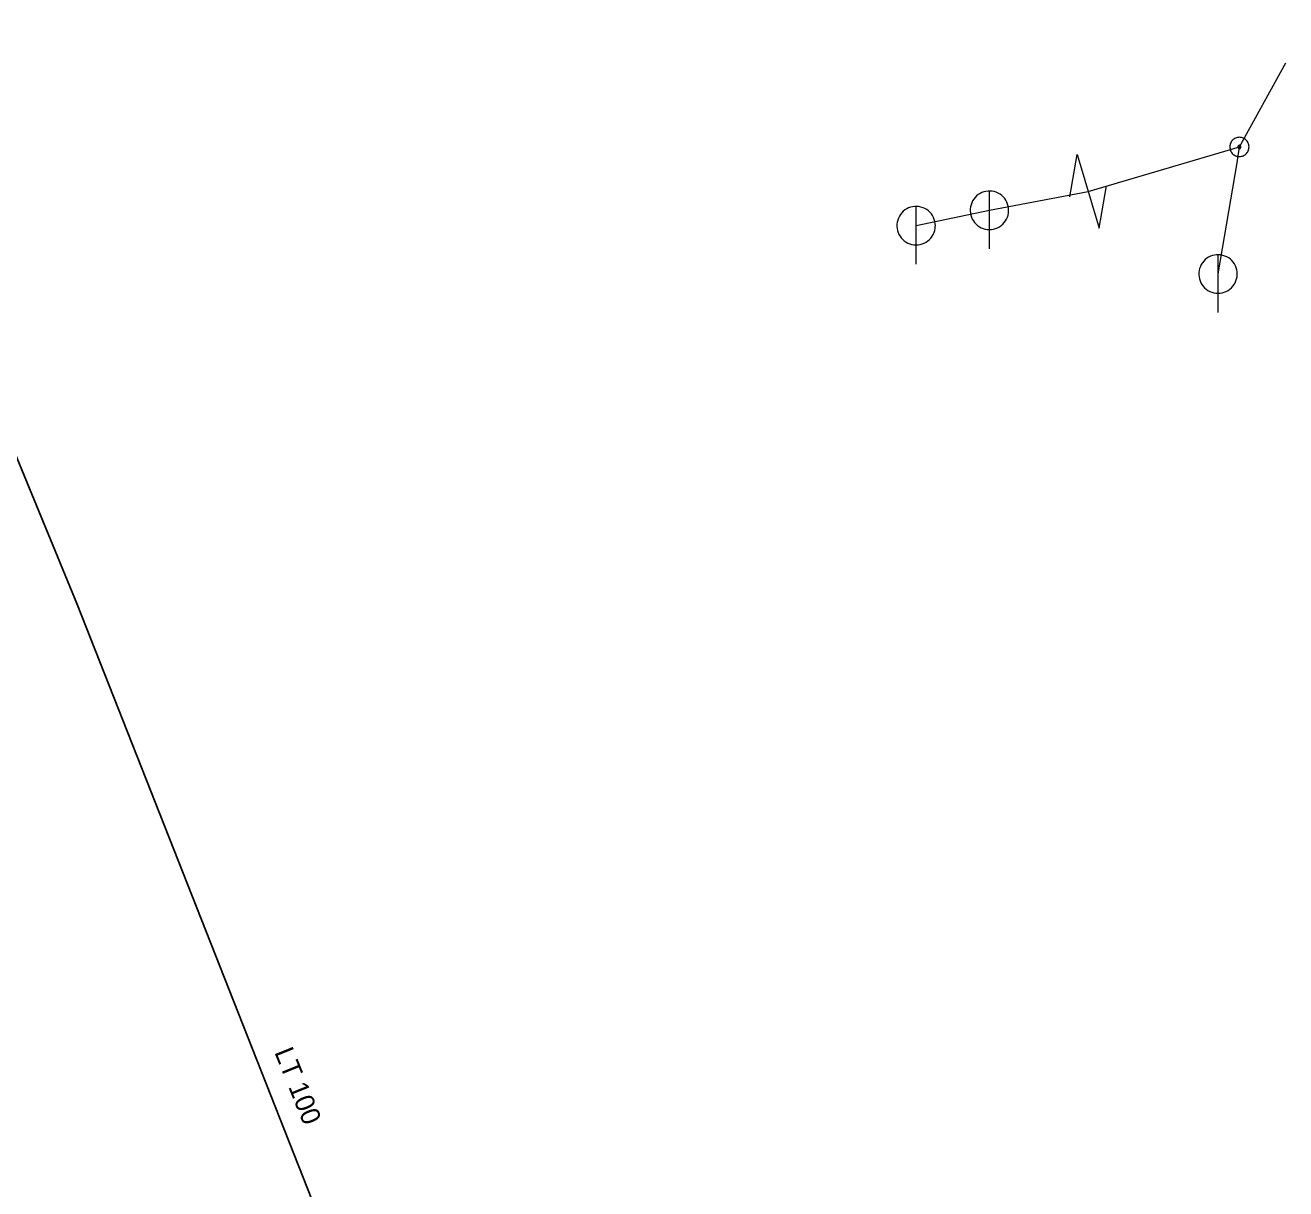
# Model space of a CAD drawing. Extents: x -690535 to -689974, y -975624 to -975325.
# Drawn here: x -690313.5 to -690248, y -975427.6 to -975367.2 of the extents above; entities that cross this region are included whole.
import ezdxf

# ---------------------------------------------------------------- set-up
doc = ezdxf.new("R2010")
doc.units = 0
doc.header["$LTSCALE"] = 0.4
for name, color, linetype, lineweight in [('1', 7, 'Continuous', 13), ('11', 7, 'Continuous', 13), ('17', 7, 'Continuous', 25), ('22', 7, 'Continuous', 13), ('31', 7, 'Continuous', 13)]:
    doc.layers.add(name, color=color, linetype=linetype, lineweight=lineweight)

msp = doc.modelspace()

# ---------------------------------------------------------------- linework, layer by layer
at = {"layer": '11'}
for points in [[(-690251.55, -975380.12), (-690250.55, -975374.35), (-690250.439, -975373.519), (-690248.029, -975369.149)], [(-690267.239, -975377.609), (-690263.43, -975376.809), (-690258.299, -975375.829), (-690250.439, -975373.519)]]:
    msp.add_lwpolyline(points, dxfattribs=at)
at = {"layer": '17'}
msp.add_lwpolyline([(-690323.245, -975367.198), (-690310.85, -975397.238), (-690289.984, -975450.151)], dxfattribs=at)
at = {"layer": '22'}
for p, q in [((-690263.43, -975378.81), (-690263.429, -975375.81)), ((-690267.24, -975379.61), (-690267.239, -975376.61)), ((-690251.55, -975382.12), (-690251.549, -975379.12))]:
    msp.add_line(p, q, dxfattribs=at)
for points in [[(-690262.43, -975376.81), (-690262.435, -975376.701), (-690262.453, -975376.593), (-690262.483, -975376.487), (-690262.523, -975376.386), (-690262.575, -975376.289), (-690262.637, -975376.199), (-690262.709, -975376.116), (-690262.789, -975376.042), (-690262.877, -975375.976), (-690262.971, -975375.921), (-690263.071, -975375.876), (-690263.176, -975375.843), (-690263.283, -975375.821), (-690263.392, -975375.811), (-690263.502, -975375.813), (-690263.61, -975375.827), (-690263.717, -975375.852), (-690263.82, -975375.889), (-690263.918, -975375.938), (-690264.01, -975375.996), (-690264.096, -975376.065), (-690264.173, -975376.142), (-690264.242, -975376.228), (-690264.301, -975376.32), (-690264.349, -975376.418), (-690264.386, -975376.521), (-690264.412, -975376.628), (-690264.426, -975376.736), (-690264.429, -975376.846), (-690264.419, -975376.955), (-690264.398, -975377.062), (-690264.364, -975377.166), (-690264.32, -975377.266), (-690264.265, -975377.361), (-690264.199, -975377.449), (-690264.125, -975377.529), (-690264.042, -975377.601), (-690263.952, -975377.663), (-690263.856, -975377.715), (-690263.754, -975377.756), (-690263.649, -975377.786), (-690263.541, -975377.804), (-690263.431, -975377.81), (-690263.322, -975377.804), (-690263.214, -975377.786), (-690263.109, -975377.757), (-690263.007, -975377.716), (-690262.91, -975377.664), (-690262.82, -975377.602), (-690262.737, -975377.531), (-690262.662, -975377.451), (-690262.597, -975377.363), (-690262.541, -975377.269), (-690262.497, -975377.169), (-690262.463, -975377.065), (-690262.441, -975376.957), (-690262.431, -975376.848)], [(-690266.24, -975377.61), (-690266.245, -975377.501), (-690266.263, -975377.393), (-690266.293, -975377.287), (-690266.333, -975377.186), (-690266.385, -975377.089), (-690266.447, -975376.999), (-690266.519, -975376.916), (-690266.599, -975376.842), (-690266.687, -975376.776), (-690266.781, -975376.721), (-690266.881, -975376.676), (-690266.986, -975376.643), (-690267.093, -975376.621), (-690267.202, -975376.611), (-690267.312, -975376.613), (-690267.42, -975376.627), (-690267.527, -975376.652), (-690267.63, -975376.689), (-690267.728, -975376.738), (-690267.82, -975376.796), (-690267.906, -975376.865), (-690267.983, -975376.942), (-690268.052, -975377.028), (-690268.111, -975377.12), (-690268.159, -975377.218), (-690268.196, -975377.321), (-690268.222, -975377.428), (-690268.236, -975377.536), (-690268.239, -975377.646), (-690268.229, -975377.755), (-690268.208, -975377.862), (-690268.174, -975377.966), (-690268.13, -975378.066), (-690268.075, -975378.161), (-690268.009, -975378.249), (-690267.935, -975378.329), (-690267.852, -975378.401), (-690267.762, -975378.463), (-690267.666, -975378.515), (-690267.564, -975378.556), (-690267.459, -975378.586), (-690267.351, -975378.604), (-690267.241, -975378.61), (-690267.132, -975378.604), (-690267.024, -975378.586), (-690266.919, -975378.557), (-690266.817, -975378.516), (-690266.72, -975378.464), (-690266.63, -975378.402), (-690266.547, -975378.331), (-690266.472, -975378.251), (-690266.407, -975378.163), (-690266.351, -975378.069), (-690266.307, -975377.969), (-690266.273, -975377.865), (-690266.251, -975377.757), (-690266.241, -975377.648)], [(-690250.55, -975380.12), (-690250.555, -975380.011), (-690250.573, -975379.903), (-690250.603, -975379.797), (-690250.643, -975379.696), (-690250.695, -975379.599), (-690250.757, -975379.509), (-690250.829, -975379.426), (-690250.909, -975379.352), (-690250.997, -975379.286), (-690251.091, -975379.231), (-690251.191, -975379.186), (-690251.296, -975379.153), (-690251.403, -975379.131), (-690251.512, -975379.121), (-690251.622, -975379.123), (-690251.73, -975379.137), (-690251.837, -975379.162), (-690251.94, -975379.199), (-690252.038, -975379.248), (-690252.13, -975379.306), (-690252.216, -975379.375), (-690252.293, -975379.452), (-690252.362, -975379.538), (-690252.421, -975379.63), (-690252.469, -975379.728), (-690252.506, -975379.831), (-690252.532, -975379.938), (-690252.546, -975380.046), (-690252.549, -975380.156), (-690252.539, -975380.265), (-690252.518, -975380.372), (-690252.484, -975380.476), (-690252.44, -975380.576), (-690252.385, -975380.671), (-690252.319, -975380.759), (-690252.245, -975380.839), (-690252.162, -975380.911), (-690252.072, -975380.973), (-690251.976, -975381.025), (-690251.874, -975381.066), (-690251.769, -975381.096), (-690251.661, -975381.114), (-690251.551, -975381.12), (-690251.442, -975381.114), (-690251.334, -975381.096), (-690251.229, -975381.067), (-690251.127, -975381.026), (-690251.03, -975380.974), (-690250.94, -975380.912), (-690250.857, -975380.841), (-690250.782, -975380.761), (-690250.717, -975380.673), (-690250.661, -975380.579), (-690250.617, -975380.479), (-690250.583, -975380.375), (-690250.561, -975380.267), (-690250.551, -975380.158)]]:
    msp.add_lwpolyline(points, close=True, dxfattribs=at)
at = {"layer": '31'}
for points in [[(-690249.939, -975373.519), (-690249.942, -975373.467), (-690249.95, -975373.414), (-690249.964, -975373.365), (-690249.982, -975373.316), (-690250.006, -975373.269), (-690250.035, -975373.225), (-690250.068, -975373.184), (-690250.105, -975373.147), (-690250.145, -975373.115), (-690250.189, -975373.086), (-690250.236, -975373.061), (-690250.285, -975373.044), (-690250.335, -975373.03), (-690250.387, -975373.022), (-690250.439, -975373.019), (-690250.491, -975373.022), (-690250.543, -975373.03), (-690250.594, -975373.044), (-690250.642, -975373.061), (-690250.689, -975373.086), (-690250.733, -975373.115), (-690250.774, -975373.147), (-690250.811, -975373.184), (-690250.844, -975373.225), (-690250.872, -975373.269), (-690250.896, -975373.316), (-690250.915, -975373.365), (-690250.928, -975373.414), (-690250.936, -975373.467), (-690250.939, -975373.519), (-690250.936, -975373.571), (-690250.928, -975373.623), (-690250.915, -975373.674), (-690250.896, -975373.722), (-690250.872, -975373.769), (-690250.844, -975373.813), (-690250.811, -975373.853), (-690250.774, -975373.891), (-690250.733, -975373.924), (-690250.689, -975373.951), (-690250.642, -975373.976), (-690250.594, -975373.995), (-690250.543, -975374.007), (-690250.491, -975374.016), (-690250.439, -975374.019), (-690250.387, -975374.016), (-690250.335, -975374.007), (-690250.285, -975373.995), (-690250.236, -975373.976), (-690250.189, -975373.951), (-690250.145, -975373.924), (-690250.105, -975373.891), (-690250.068, -975373.853), (-690250.035, -975373.813), (-690250.006, -975373.769), (-690249.982, -975373.722), (-690249.964, -975373.674), (-690249.95, -975373.623), (-690249.942, -975373.571)], [(-690250.357, -975373.519), (-690250.357, -975373.51), (-690250.359, -975373.502), (-690250.361, -975373.494), (-690250.364, -975373.485), (-690250.368, -975373.478), (-690250.373, -975373.471), (-690250.378, -975373.463), (-690250.384, -975373.458), (-690250.391, -975373.453), (-690250.398, -975373.448), (-690250.406, -975373.444), (-690250.414, -975373.441), (-690250.422, -975373.439), (-690250.43, -975373.436), (-690250.439, -975373.436), (-690250.448, -975373.436), (-690250.456, -975373.439), (-690250.464, -975373.441), (-690250.472, -975373.444), (-690250.48, -975373.448), (-690250.487, -975373.453), (-690250.494, -975373.458), (-690250.5, -975373.463), (-690250.506, -975373.471), (-690250.51, -975373.478), (-690250.514, -975373.485), (-690250.517, -975373.494), (-690250.519, -975373.502), (-690250.521, -975373.51), (-690250.521, -975373.519), (-690250.521, -975373.527), (-690250.519, -975373.536), (-690250.517, -975373.544), (-690250.514, -975373.552), (-690250.51, -975373.559), (-690250.506, -975373.566), (-690250.5, -975373.574), (-690250.494, -975373.58), (-690250.487, -975373.586), (-690250.48, -975373.59), (-690250.472, -975373.593), (-690250.464, -975373.597), (-690250.456, -975373.598), (-690250.448, -975373.601), (-690250.439, -975373.601), (-690250.43, -975373.601), (-690250.422, -975373.598), (-690250.414, -975373.597), (-690250.406, -975373.593), (-690250.398, -975373.59), (-690250.391, -975373.586), (-690250.384, -975373.58), (-690250.378, -975373.574), (-690250.373, -975373.566), (-690250.368, -975373.559), (-690250.364, -975373.552), (-690250.361, -975373.544), (-690250.359, -975373.536), (-690250.357, -975373.527)]]:
    msp.add_lwpolyline(points, close=True, dxfattribs=at)
msp.add_lwpolyline([(-690259.258, -975376.111), (-690258.862, -975373.91), (-690257.734, -975377.748), (-690257.339, -975375.547)], dxfattribs=at)

# ---------------------------------------------------------------- texts
at = {"layer": '1'}
msp.add_text('LT 100', height=1, rotation=292, dxfattribs=at).set_placement((-690300.6, -975420.542))

doc.saveas('drawing.dxf')
